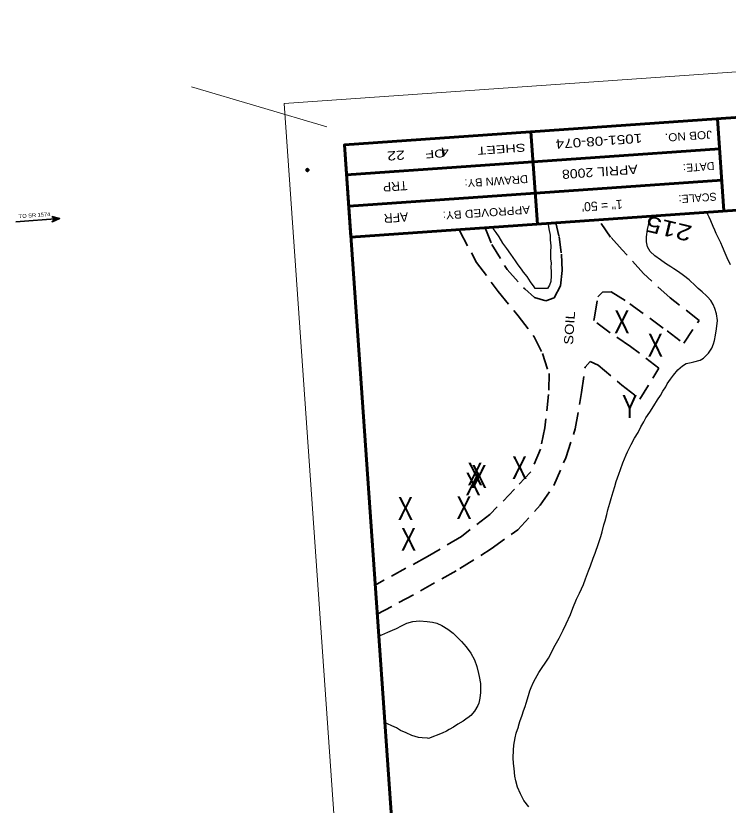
# Model space of a CAD drawing. Extents: x 2399800 to 2400616, y 567351 to 568869.
# Drawn here: x 2399799.6 to 2400111.3, y 568508.2 to 568853.9 of the extents above; entities that cross this region are included whole.
import ezdxf
from ezdxf.enums import TextEntityAlignment as Align

# ---------------------------------------------------------------- set-up
doc = ezdxf.new("R2010")
doc.units = 0
doc.header["$LTSCALE"] = 2.4
doc.header["$PDMODE"] = 32
doc.header["$PDSIZE"] = 1.2
doc.linetypes.add('MEDIUM_DASHED', pattern=[4.5, 3, -1.5])
for name, color, linetype, lineweight in [('10', 7, 'Continuous', 35), ('11', 7, 'Continuous', 25), ('27', 7, 'Continuous', 80), ('3', 7, 'MEDIUM_DASHED', 35), ('61', 7, 'Continuous', 40), ('63', 7, 'Continuous', 35)]:
    doc.layers.add(name, color=color, linetype=linetype, lineweight=lineweight)
doc.layers.add('23', color=7, linetype='Continuous')

msp = doc.modelspace()

# ---------------------------------------------------------------- hatches: boundary and pattern name
at = {"layer": '10'}
msp.add_hatch(color=256, dxfattribs=at).paths.add_polyline_path([(2399815.265, 568765.953), (2399818.71, 568765.066), (2399815.422, 568763.708), (2399816.466, 568764.909)])

# ---------------------------------------------------------------- linework, layer by layer
msp.add_lwpolyline([(2399815.265, 568765.953), (2399818.71, 568765.066), (2399815.422, 568763.708), (2399816.466, 568764.909)], close=True, dxfattribs=at)
at = {"layer": '11'}
for points in [[(2400081.651, 568746.964), (2400079.227, 568748.804), (2400077.188, 568750.67), (2400076.011, 568752.728), (2400075.537, 568754.922), (2400075.587, 568757.047), (2400076.009, 568760.266), (2400076.665, 568763.53), (2400077.383, 568766.101), (2400077.409, 568766.179)], [(2400101.855, 568767.889), (2400102.775, 568765.818), (2400103.562, 568764.269), (2400104.615, 568761.846), (2400105.242, 568760.241), (2400105.954, 568758.701), (2400107.017, 568756.354), (2400107.933, 568754.635), (2400108.691, 568752.861), (2400109.845, 568750.045), (2400110.722, 568748.027), (2400112.146, 568744.947)], [(2400032.444, 568763.035), (2400032.645, 568761.685), (2400032.817, 568760.673), (2400033.352, 568757.786), (2400033.462, 568755.716), (2400033.661, 568753.177), (2400033.598, 568750.368), (2400033.6, 568747.475), (2400033.803, 568745.545), (2400033.737, 568743.878), (2400033.856, 568741.883), (2400033.836, 568739.983), (2400033.737, 568737.483), (2400033.081, 568735.97), (2400032.192, 568734.412), (2400026.799, 568734.509)], [(2400026.799, 568734.509), (2400026.354, 568735.177), (2400024.822, 568737.433), (2400023.291, 568739.689), (2400021.71, 568741.572), (2400021.07, 568742.493), (2400019.073, 568745.267), (2400018.182, 568746.602), (2400016.13, 568749.536), (2400014.394, 568751.971), (2400012.732, 568754.397), (2400011.035, 568757.132), (2400009.753, 568758.975), (2400008.853, 568760.235), (2400008.184, 568761.339)], [(2400019.482, 568542.518), (2400019.561, 568542.757), (2400020.135, 568544.813), (2400021.116, 568547.654), (2400021.736, 568549.476), (2400022.44, 568551.363), (2400022.945, 568552.896), (2400023.921, 568556.27), (2400024.56, 568558.243), (2400025.13, 568559.69), (2400026.118, 568561.997), (2400026.952, 568563.715), (2400028.503, 568566.253), (2400029.581, 568568.091), (2400031.536, 568570.804), (2400032.604, 568572.568), (2400034.11, 568575.34), (2400035.038, 568577.198), (2400037.329, 568581.313), (2400039.092, 568584.889), (2400040.362, 568587.616), (2400042.269, 568591.706), (2400043.316, 568594.461), (2400044.903, 568598.441), (2400046.239, 568601.083), (2400047.956, 568604.893), (2400048.814, 568607.37), (2400050.183, 568610.845), (2400051.001, 568613.022), (2400052.276, 568616.357), (2400053.094, 568618.534), (2400054.487, 568622.767), (2400055.497, 568625.832), (2400056.081, 568627.964), (2400056.848, 568630.909), (2400057.393, 568632.741), (2400058.214, 568635.526), (2400058.704, 568637.518), (2400059.555, 568640.528), (2400060.11, 568642.434), (2400060.961, 568645.444), (2400061.639, 568647.716), (2400062.308, 568649.912), (2400063.488, 568653.108), (2400064.137, 568655.155), (2400065.203, 568658.06), (2400065.897, 568659.873), (2400066.657, 568661.601), (2400067.292, 568662.964), (2400068.846, 568666.11), (2400070.277, 568668.892), (2400071.902, 568671.42), (2400073.134, 568673.847), (2400074.337, 568676.049), (2400075.33, 568677.823), (2400076.956, 568680.351), (2400078.771, 568683.158), (2400080.406, 568685.761), (2400081.644, 568687.655), (2400082.722, 568689.493), (2400083.97, 568691.461), (2400084.661, 568692.665), (2400086.003, 568694.773), (2400087.381, 568696.572), (2400089.276, 568698.836), (2400091.337, 568700.622), (2400092.907, 568701.558), (2400095.111, 568702.106), (2400096.217, 568702.418), (2400098.965, 568703.048), (2400100.534, 568703.985), (2400102.013, 568705.39), (2400102.644, 568706.144), (2400104.156, 568708.383), (2400104.86, 568710.27), (2400105.356, 568711.728), (2400105.809, 568714.028), (2400106.257, 568716.863), (2400106.569, 568720.4), (2400106.127, 568723.427), (2400105.439, 568725.726), (2400104.672, 568727.425), (2400103.68, 568729.154), (2400102.22, 568730.792), (2400101.83, 568731.3), (2400099.855, 568733.081), (2400098.216, 568734.515), (2400096.986, 568735.589), (2400094.212, 568738.237), (2400091.798, 568740.152), (2400089.57, 568741.738), (2400087.546, 568743.146), (2400086.202, 568743.931), (2400083.814, 568745.462), (2400081.651, 568746.964)], [(2399958.407, 568582.339), (2399959.788, 568582.796), (2399962.294, 568583.914), (2399964.388, 568584.782), (2399966.172, 568585.614), (2399968.369, 568586.696), (2399970.726, 568587.834), (2399973.269, 568588.643), (2399976.192, 568588.869), (2399979.515, 568588.662), (2399981.835, 568588.358), (2399983.761, 568587.953), (2399986.058, 568586.89), (2399988.671, 568585.33), (2399990.88, 568583.594), (2399992.425, 568582.021), (2399994.66, 568579.901), (2399996.705, 568577.501), (2399998.627, 568574.736), (2400000.22, 568571.787), (2400001.289, 568568.906), (2400002.029, 568565.84), (2400002.386, 568564.498), (2400002.837, 568561.546), (2400002.979, 568560.309), (2400002.851, 568557.585), (2400002.602, 568555.105), (2400002.148, 568552.804), (2400001.786, 568551.786), (2400000.255, 568549.398), (2399998.623, 568547.404), (2399997.353, 568546.429), (2399997.12, 568546.264)], [(2399980.183, 568537.41), (2399979.659, 568537.479), (2399977.394, 568537.624), (2399975.747, 568537.84), (2399972.896, 568538.746), (2399970.45, 568539.828), (2399967.928, 568540.92), (2399966.09, 568541.998), (2399964.082, 568542.947), (2399962.149, 568543.885), (2399961.061, 568544.391)], [(2399997.12, 568546.264), (2399995.257, 568544.952), (2399993.03, 568543.645), (2399991.027, 568542.309), (2399989.139, 568541.262), (2399988.058, 568540.566), (2399986.114, 568539.679), (2399980.183, 568537.41)], [(2400017.587, 568524.209), (2400017.422, 568526.439), (2400017.212, 568528.903), (2400017.345, 568532.236), (2400017.554, 568534.416), (2400018.051, 568537.625), (2400018.55, 568539.691), (2400019.482, 568542.518)], [(2400023.995, 568507.457), (2400021.923, 568510.241), (2400020.396, 568513.106), (2400019.102, 568516.017), (2400018.332, 568518.858), (2400017.998, 568520.958), (2400017.587, 568524.209)]]:
    msp.add_lwpolyline(points, dxfattribs=at)
at = {"layer": '27', "lineweight": 35}
msp.add_line((2399818.71, 568765.066), (2399799.553, 568763.726), dxfattribs=at)
at = {"layer": '3'}
msp.add_line((2400037.25, 568757.607), (2400035.887, 568763.276), dxfattribs=at)
for points in [[(2400054.226, 568730.801), (2400056.242, 568732.821), (2400060.082, 568733.079), (2400068.3, 568727.814), (2400084.55, 568715.863), (2400091.84, 568710.492), (2400098.558, 568720.499), (2400085.844, 568730.387), (2400074.222, 568741.047), (2400064.93, 568751.478), (2400059.869, 568757.014), (2400054.546, 568764.581)], [(2399993.512, 568760.313), (2399993.805, 568759.57), (2400001.149, 568745.893), (2400010.68, 568733.223), (2400019.399, 568722.487), (2400026.424, 568713.344), (2400030.022, 568705.944), (2400032.911, 568697.191), (2400032.706, 568688.081), (2400031.093, 568673.446), (2400029.183, 568664.103), (2400024.816, 568654.016), (2400017.823, 568646.557), (2400007.008, 568635.488), (2399994.563, 568625.927), (2399979.772, 568617.054), (2399960.609, 568606.775), (2399956.854, 568604.555)], [(2400004.925, 568761.111), (2400007.891, 568753.765), (2400014.52, 568742.77), (2400022.241, 568734.297), (2400026.545, 568730.535), (2400031.527, 568729.045), (2400035.131, 568730.4), (2400037.868, 568735.599), (2400038.676, 568742.345), (2400038.254, 568750.167), (2400037.25, 568757.607)], [(2400052.462, 568720.444), (2400052.749, 568721.924), (2400054.226, 568730.801)], [(2400048.706, 568700.076), (2400050.846, 568702.46), (2400054.442, 568700.847), (2400064.717, 568692.115), (2400072.678, 568686.047), (2400081.008, 568699.65), (2400068.621, 568709.115), (2400059.583, 568715.096), (2400052.462, 568720.444)], [(2399957.747, 568591.782), (2399976.583, 568602.017), (2399993.851, 568611.783), (2400007.621, 568620.41), (2400019.225, 568628.786), (2400029.084, 568639.524), (2400035.025, 568648.262), (2400040.181, 568660.301), (2400044.359, 568673.002), (2400047.121, 568688.856), (2400048.706, 568700.076)]]:
    msp.add_lwpolyline(points, dxfattribs=at)
msp.add_point((2399927.172, 568786.363), dxfattribs=at)
at = {"layer": '63', "lineweight": 13}
for p, q in [((2399917.038, 568815.546), (2400465.699, 568853.912)), ((2399935.688, 568805.343), (2399876.368, 568822.792)), ((2399917.038, 568815.546), (2399976.331, 567967.616))]:
    msp.add_line(p, q, dxfattribs=at)
at = {"layer": '63'}
msp.add_line((2400442.155, 568832.216), (2399943.373, 568797.338), dxfattribs=at)
at = {"layer": '63', "lineweight": 60}
for p, q in [((2400106.636, 568808.755), (2400109.456, 568768.421)), ((2400027.825, 568762.712), (2400025.004, 568803.046)), ((2399999.405, 567996.031), (2399943.373, 568797.338)), ((2400107.548, 568795.711), (2399944.285, 568784.294)), ((2400108.512, 568781.927), (2399945.249, 568770.51))]:
    msp.add_line(p, q, dxfattribs=at)
msp.add_lwpolyline([(2400444.975, 568791.882), (2399946.193, 568757.004), (2399943.373, 568797.338), (2400442.155, 568832.216)], close=True, dxfattribs=at)

# ---------------------------------------------------------------- texts
at = {"layer": '11', "width": 0.75}
for s, p in [('X', (2400064.758, 568714.872)), ('X', (2400079.408, 568704.653)), ('Y', (2400068.199, 568677.799)), ('X', (2400019.994, 568650.998)), ('X', (2400000.52, 568648.22)), ('X', (2400002.283, 568647.152)), ('X', (2399999.642, 568643.843)), ('X', (2399970.063, 568633.101)), ('X', (2399995.694, 568633.473)), ('X', (2399971.416, 568619.6))]:
    msp.add_text(s, height=10, dxfattribs=at).set_placement(p, align=Align.CENTER)
at = {"layer": '23'}
for s, height, rotation, width, p in [('TO SR 1574', 1.688, 4, 1.1, (2399807.812, 568765.715)), ('SOIL', 4, 86.307, 1.2, (2400043.85, 568717.035))]:
    msp.add_text(s, height=height, rotation=rotation, dxfattribs=dict(at, width=width)).set_placement(p, align=Align.CENTER)
at = {"layer": '61', "width": 1.3}
msp.add_text('215', height=7, rotation=166.537, dxfattribs=at).set_placement((2400086.096, 568764.076), align=Align.CENTER)
at = {"layer": '63'}
for s, width, p in [('JOB NO.', 1.1, (2400104.064, 568803.677)), ('SHEET        OF', 1.35, (2400022.433, 568797.968)), ('DRAWN BY:', 1.05, (2400023.551, 568784.198)), ('APPROVED BY:', 1.1, (2400024.489, 568770.785))]:
    msp.add_text(s, height=3.5, rotation=184, dxfattribs=dict(at, width=width)).set_placement(p)
for s, width, p in [('1051-08-074', 1.25, (2400054.604, 568800.99)), ('4        22', 1.3, (2399975.454, 568795.377)), ('APRIL 2008', 1.15, (2400054.992, 568787.551))]:
    msp.add_text(s, height=4, rotation=184, dxfattribs=dict(at, width=width)).set_placement(p, align=Align.CENTER)
for s, p in [('DATE:', (2400105.162, 568789.905)), ('SCALE:', (2400106.1, 568776.492))]:
    msp.add_text(s, height=3.5, rotation=184, dxfattribs=at).set_placement(p)
for s, p in [('TRP', (2399965.437, 568781.21)), ('1" = 50\'', (2400056.026, 568772.767)), ('AFR', (2399965.78, 568767.504))]:
    msp.add_text(s, height=4, rotation=184, dxfattribs=at).set_placement(p, align=Align.CENTER)

doc.saveas('drawing.dxf')
